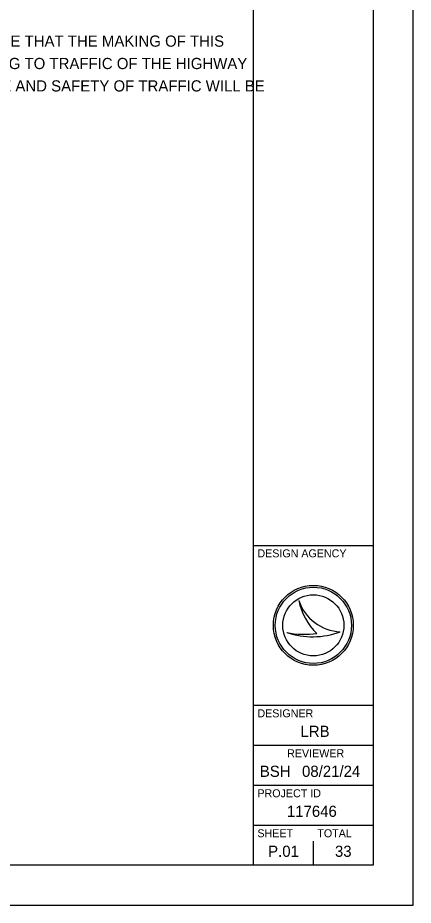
# Model space of a CAD drawing. Extents: x -3.3 to 34, y 0 to 56.8.
# Drawn here: x 29.05 to 34, y 0 to 11.1 of the extents above; entities that cross this region are included whole.
import ezdxf

# ---------------------------------------------------------------- set-up
doc = ezdxf.new("R2010")
doc.units = 0
for name, color, linetype in [('SH_Border', 7, 'Continuous'), ('SH_Cut_Line', 7, 'Continuous'), ('SH_Data', 7, 'Continuous'), ('SH_Major_Grid_Line', 7, 'Continuous')]:
    doc.layers.add(name, color=color, linetype=linetype)

msp = doc.modelspace()

# ---------------------------------------------------------------- linework, layer by layer
at = {"layer": 'SH_Border'}
msp.add_lwpolyline([(0, 0), (34, 0), (34, 22), (0, 22)], close=True, dxfattribs=at)
at = {"layer": 'SH_Cut_Line'}
for p, q in [((32, 0.5), (32, 21.5)), ((32, 4.5), (33.5, 4.5)), ((32, 2.5), (33.5, 2.5)), ((32, 2), (33.5, 2)), ((32, 1.5), (33.5, 1.5)), ((32, 1), (33.5, 1))]:
    msp.add_line(p, q, dxfattribs=at)
msp.add_lwpolyline([(1.5, 21.5), (33.5, 21.5), (33.5, 0.5), (1.5, 0.5)], close=True, dxfattribs=at)
at = {"layer": 'SH_Data'}
for p, q in [((32.567, 3.81), (32.567, 3.81)), ((32.75, 3.5), (32.75, 3.5)), ((32.417, 3.41), (32.417, 3.41)), ((33.087, 3.419), (33.087, 3.419)), ((32.75, 0.5), (32.75, 0.8)), ((32.375, 0.675), (32.375, 0.675))]:
    msp.add_line(p, q, dxfattribs=at)
for radius in [0.5, 0.477, 0.477, 0.382]:
    msp.add_circle((32.75, 3.5), radius, dxfattribs=at)
for centre, radius, start, end in [((33.116, 3.998), 0.58, 198.9257, 198.9319), ((33.347, 3.97), 0.796, 191.6379, 191.6421), ((33.116, 3.998), 0.58, 198.9319, 267.1657), ((33.347, 3.97), 0.796, 191.6421, 226.0947), ((32.739, 4.37), 1.013, 251.4576, 290.0832), ((32.648, 4.654), 1.266, 259.4964, 259.4995), ((32.739, 4.37), 1.013, 251.4527, 251.4576), ((32.648, 4.654), 1.266, 259.4995, 276.6672)]:
    msp.add_arc(centre, radius, start, end, dxfattribs=at)

# ---------------------------------------------------------------- texts
for s, height, p in [('DESIGN AGENCY', 0.1, (32.05, 4.35)), ('DESIGNER', 0.1, (32.05, 2.35)), ('LRB', 0.14, (32.589, 2.105)), ('REVIEWER', 0.1, (32.422, 1.85)), ('BSH', 0.14, (32.08, 1.605)), ('08/21/24', 0.14, (32.608, 1.605)), ('PROJECT ID', 0.1, (32.05, 1.35)), ('117646', 0.14, (32.419, 1.105)), ('SHEET', 0.1, (32.05, 0.85)), ('TOTAL', 0.1, (32.8, 0.85)), ('P.01', 0.14, (32.184, 0.605)), ('33', 0.14, (33.02, 0.605))]:
    msp.add_text(s, height=height, dxfattribs=at).set_placement(p)
at = {"layer": 'SH_Major_Grid_Line'}
for s, p in [('I HEREBY APPROVE THESE PLANS AND DECLARE THAT THE MAKING OF THIS ', (24.528, 10.735)), ('IMPROVEMENT WILL NOT REQUIRE THE CLOSING TO TRAFFIC OF THE HIGHWAY ', (24.528, 10.455)), ('AND THAT PROVISIONS FOR THE MAINTENANCE AND SAFETY OF TRAFFIC WILL BE ', (24.528, 10.175))]:
    msp.add_text(s, height=0.14, dxfattribs=at).set_placement(p)

doc.saveas('drawing.dxf')
